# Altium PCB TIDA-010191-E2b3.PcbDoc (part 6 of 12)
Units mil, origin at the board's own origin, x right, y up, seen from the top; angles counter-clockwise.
Board outline 9842.52 x 9842.4 mil, 6 copper layers (Layer 1 - Top Layer, Layer 2 - GND Layer, Layer 3 - Signal, Layer 4 - Signal, Layer 5 - GND, Bottom Layer), stack 59.9 mil thick; 1178 components, 642 nets, 3329 pads, 2967 vias.
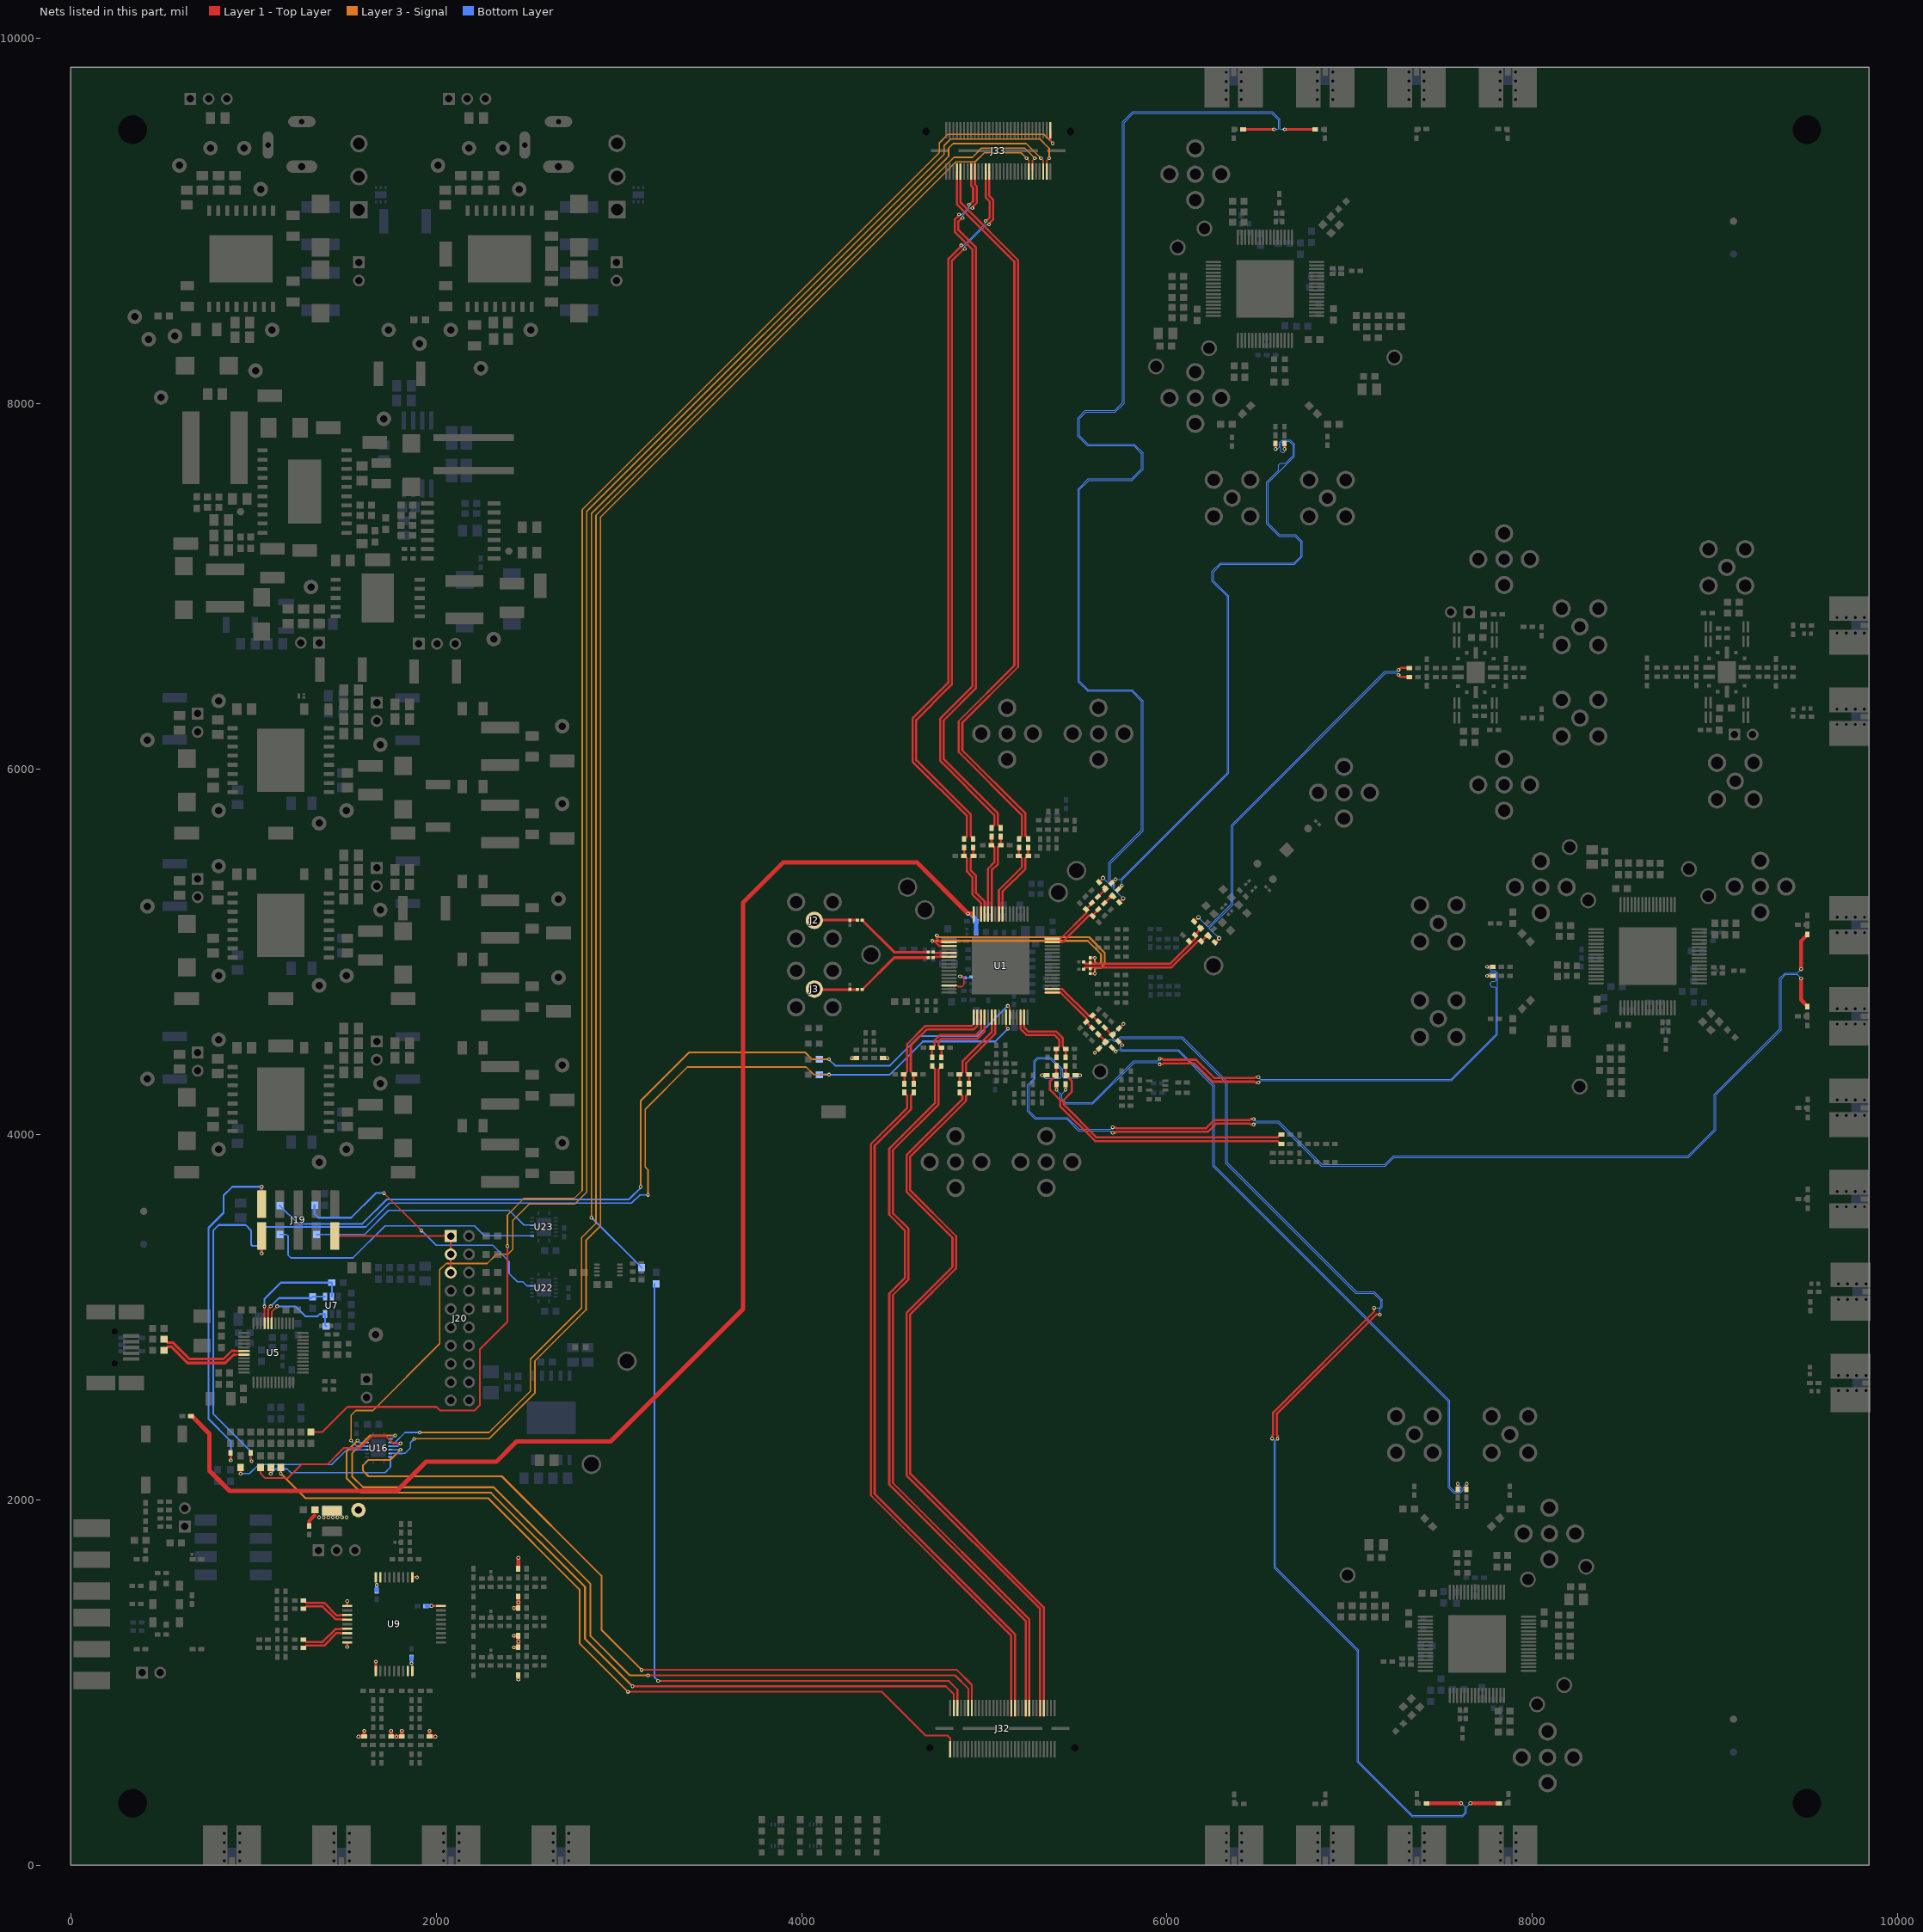
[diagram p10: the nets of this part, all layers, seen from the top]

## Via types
v1: diameter 20, hole 10, Layer 1 - Top Layer to Bottom Layer, tented both sides, 2595 vias
v2: diameter 19.68, hole 7.87, Layer 1 - Top Layer to Bottom Layer, 308 vias
v3: diameter 19.68, hole 7.87, Layer 1 - Top Layer to Bottom Layer, tented both sides, 25 vias
v4: diameter 20, hole 10, Layer 1 - Top Layer to Bottom Layer, 21 vias
v5: diameter 41, hole 25, Layer 1 - Top Layer to Bottom Layer, 10 vias
v6: diameter 24, hole 12, Layer 1 - Top Layer to Bottom Layer, tented both sides, 4 vias
v7: diameter 24, hole 8, Layer 1 - Top Layer to Bottom Layer, tented both sides, 1 vias
v8: diameter 24/24/24/24/24/24 (per signal layer), hole 8, Layer 1 - Top Layer to Bottom Layer, tented both sides, 1 vias
v9: diameter 30, hole 12, Layer 1 - Top Layer to Bottom Layer, tented both sides, 1 vias
v10: diameter 20/20/20/20/20/20 (per signal layer), hole 10, Layer 1 - Top Layer to Bottom Layer, tented both sides, 1 vias

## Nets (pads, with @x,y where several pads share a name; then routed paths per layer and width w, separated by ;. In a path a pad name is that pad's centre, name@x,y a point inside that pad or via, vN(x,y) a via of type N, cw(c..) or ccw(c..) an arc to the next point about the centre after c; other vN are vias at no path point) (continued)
C_VCC: C93.1 C94.1 C95.1 C96.1 C97.1 L17.2 R175.2 R395.2 R396.2 R428.2 R429.2 R438.2 R439.2 R448.2 R449.2 R458.2 R459.2 R468.2 R469.2 TP8.1 U9.1 U9.9 U9.10 U9.17 U9.18 U9.27 U9.28 U9.35 U9.36 | length 923.2
  Layer 1 - Top Layer w12: v1(1513.58,1195) U9.9@1513.58,1220.48 ; U9.1@1513.58,1420.48 v1(1513.58,1445.96) ; U9.10@1670.08,1063.98 v1(1670.08,1115.56) ; U9.28@1870.08,1576.98 v1(1895.56,1576.98) ; v1(1975,1420.48) U9.27@2026.58,1420.48
  Layer 1 - Top Layer w20: R175.2@1305,1858.62 1305,1885 1335,1915 ; v1(1575.09,705) R396.2@1606.38,705 v1(1606.38,736.28) ; v1(1753.62,736.28) R395.2@1753.62,705 v1(1783,705) R429.2@1812.38,705 v1(1812.38,736.28) ; v1(1964.62,736.28) R428.2@1964.62,705 v1(1995.91,705) ; v1(2425,1193.62) R469.2@2450,1193.62 v1(2450,1225) R459.2@2450,1256.38 v1(2425,1256.38) ; v1(2425,1408.62) R458.2@2450,1408.62 v1(2450,1440) R449.2@2450,1471.38 ; v1(2450,1016.38) R468.2@2450,1041.38 ; R448.2@2450,1623.62 v1(2450,1683.54) ; v1(4275.38,4418.76) R438.2@4300.38,4418.76 ; R439.2@4444.62,4418.76 v1(4469.62,4418.76)
  Bottom Layer w20: C95.1@1675,1503.62 v1(1675,1535) ; v1(1865.15,1105.96) C97.1@1865.15,1137.34 ; C96.1@1945,1420 1945.48,1420.48 v1(1975,1420.48)
  other v1: 1360,1905 1385,1905 1410,1905 1435,1905 1460,1905 1485,1905 1510,1905
CDCLVP_CLK1_N: R220.2 U9.7 | length 275
  Layer 1 - Top Layer w12: R220.2@1273.62,1190.96 1277.56,1190.96 1290.06,1203.46 1386.78,1203.46 1456.3,1272.98 1476.98,1272.98 1479.48,1270.48 U9.7@1513.58,1270.48
CDCLVP_CLK1_P: R180.2 U9.6 | length 275
  Layer 1 - Top Layer w12: R180.2@1273.62,1235.96 1277.56,1235.96 1290.06,1223.46 1378.5,1223.46 1448.02,1292.98 1477.02,1292.98 1479.52,1295.48 U9.6@1513.58,1295.48
CDCM7005-SP_VCXO_IN_N: R36.2 U9.4 | length 275
  Layer 1 - Top Layer w12: R36.2@1273.62,1405 1277.56,1405 1290.06,1417.5 1378.5,1417.5 1448.02,1347.98 1477.02,1347.98 1479.52,1345.48 U9.4@1513.58,1345.48
CDCM7005-SP_VCXO_IN_P: R38.2 U9.3 | length 275
  Layer 1 - Top Layer w12: R38.2@1273.62,1450 1277.56,1450 1290.06,1437.5 1386.78,1437.5 1456.3,1367.98 1476.98,1367.98 1479.48,1370.48 U9.3@1513.58,1370.48
CLKIN0_N: C37.2 U1.38 | length 81.2
  Layer 1 - Top Layer w12: C37.2@4719.88,4969.09 4722.15,4971.36 4725.36,4971.36 4728.09,4974.09 U1.38@4799.04,4974.09
CLKIN0_P: C36.2 U1.37 | length 89.5
  Layer 1 - Top Layer w12: C36.2@4719.88,4999.09 4722.15,4996.83 4725.17,4996.83 4727.9,4994.09 U1.37@4807.32,4994.09
CLKin1_N: R556.2 U1.35 | length 1191
  Layer 1 - Top Layer w12: v1@4715,5060 4726.72,5060 4753.45,5033.27 U1.35@4807.52,5033.27 ; R556.2@5580,4967.99 v1@5604.9,4967.99
  Layer 3 - Signal w10.5: v1(4715.42,5060.42) 5566.2,5060.42 5639.41,4987.21 5639.41,4943.28 5631.12,4935 5616,4935 5605.17,4945.83 v1(5605.17,4967.99)
CLKIN1_P: R555.2 U1.34 | length 1260.7
  Layer 1 - Top Layer w12: v1@4740,5090 4740,5075 4762,5053 U1.34@4844,5053 ; R555.2@5580,4882.01 v1@5604.9,4882.01
  Layer 3 - Signal w10.5: v1(4740.42,5089.66) 4749.02,5081.06 5573.83,5081.06 5659.41,4995.48 5659.41,4935 5639.41,4915 5616,4915 5605.17,4904.17 v1(5605.17,4882.01)
CLKin1c_N: C39.2 C40.2 C80.2 R145.2 R554.1 R556.1 | length 740.5
  Layer 1 - Top Layer w12: R554.1@5542.99,4945 5553.15,4934.84 6016.56,4934.84 6155,5073.28 6155,5094.96 C39.2@6187.04,5127
CLKin1c_P: C38.2 C79.2 R145.1 R553.1 R555.1 | length 755.2
  Layer 1 - Top Layer w12: R553.1@5542.99,4905 5553.15,4915.16 6024.71,4915.16 R145.1@6168.92,5059.36 ; R145.1@6170,5060 6190.04,5060 C38.2@6222.04,5092
CLKin1d_N: C80.1 R131.2 | length 2048.6
  Layer 1 - Top Layer w4.25: v6@6171.21,5189.62 v6(6171.89,5189.62)
  Layer 1 - Top Layer w12: C80.1@6148.3,5166.7 v6@6171.21,5189.62 ; v1(7267,6543.5) 7278.5,6555 R131.2@7326.38,6555
  Bottom Layer w4.25: v6(6171.89,5189.62) 6223.37,5138.14 6226.89,5138.14 6351.75,5263 6351.75,5694.62 7192.38,6535.25 7256.87,6535.25 7265.12,6543.5 v1(7267,6543.5)
CLKin1d_P: C79.1 R121.2 | length 2044
  Layer 1 - Top Layer w12: C79.1@6261.7,5053.3 v6@6284.4,5075.99 ; v1(7267,6516.5) 7278.5,6505 R121.2@7326.38,6505
  Bottom Layer w4.25: v6(6285.23,5075.08) 6232.83,5127.48 6232.83,5131 6361,5259.17 6361,5690.79 7196.21,6526 7257.5,6526 v1(7267,6516.5) v1@7265.62,6516.5
CLKIN_SEL0: R78.1 R296.2 U1.58 | length 5018.6
  Layer 1 - Top Layer w8: U1.58@5119.53,4642.52 5119.53,4590.47 5129,4581 v1(5129,4580)
  Layer 3 - Signal w8: v1(3160,3670.59) 3160,3807.25 3144,3823.25 3144,4139 3375,4370 4025,4370 4066.54,4328.46 v1(4150,4328.46)
  Bottom Layer w8: R296.2@1045,3454.06 1045,3485 1055,3495 1615,3495 1745,3625 3070,3625 3115.59,3670.59 v1(3160,3670.59)
  Bottom Layer w10: v1(4150,4328.46) 4482.84,4328.46 4664.38,4510 5060,4510 5129,4579 v1(5129,4580)
  Bottom Layer w10.5: R78.1@4098.39,4328.46 v1(4150,4328.46)
CLKIN_SEL1: R77.1 R307.1 U1.59 | length 4983
  Layer 1 - Top Layer w8: v1(5128.74,4705.04) 5139.21,4694.57 U1.59@5139.21,4642.52
  Layer 3 - Signal w10: v1(3120,3715) 3120,4185 3385,4450 4020,4450 4058,4412 v1(4150,4412)
  Bottom Layer w10: R307.1@1145,3611.56 1245,3511.56 1596.56,3511.56 1730,3645 3055,3645 3125,3715 v1(3120,3715) ; v1(4150,4412) 4184,4378 4484,4378 4646,4540 4963.7,4540 v1(5128.74,4705.04)
  Bottom Layer w10.5: R77.1@4098.39,4412 v1(4150,4412)
CLKINN0: J3.1 R100.1 R101.1 | length 237.1
  Layer 1 - Top Layer w15: J3.1@4073.26,4793.74 R101.1@4305.75,4793.74
  Layer 1 - Top Layer w24: J3.1@4070,4797 J3.1@4073.26,4793.74
CLKINN1: C37.1 R101.2 | length 430.9
  Layer 1 - Top Layer w15: R101.2@4331.73,4793.74 4507.09,4969.09 C37.1@4690,4969.09
CLKINP0: J2.1 R98.1 R99.2 | length 232.5
  Layer 1 - Top Layer w15: J2.1@4073.26,5174.45 R98.1@4305.75,5174.45
CLKINP1: C36.1 R98.2 | length 430.9
  Layer 1 - Top Layer w15: R98.2@4331.73,5174.45 4507.09,4999.09 C36.1@4690,4999.09
CPOUT1: C17.1 C186.2 R33.2 U1.32 | length 7542.1
  Layer 1 - Top Layer w24: R33.2@658.62,2460 662.56,2460 760,2362.56 760,2160 870,2050 1785,2050 1945,2210 2330,2210 2440,2320 2955,2320 3680,3045 3680,5270 3900,5490 4631.65,5490 v1@4911.21,5210.44 ; v1(4911.41,5209.62) 4936.27,5209.62
  Bottom Layer w24: v1@4912.64,5209.82 4924.48,5209.82 4949.57,5184.73 4949.57,5168.76 4949.76,5168.58 C17.1@4953.32,5168.58 4954.62,5168.58 4954.81,5168.39 4954.81,5105.19 C186.2@4955,5105
CPOUT2: C7.1 C8.2 U1.46 | length 218.5
  Layer 1 - Top Layer w8: U1.46@4807.52,4816.73 4808.25,4816 4853.57,4816 4859.85,4809.72 4877.83,4809.72 4887.73,4819.62 4887.73,4860.82 4882.19,4866.36 v1(4866.97,4866.36)
  Bottom Layer w8: v1@4866.8,4865.99 4870.58,4865.99 4878.32,4858.26 C8.2@4894.36,4858.26 4905.63,4858.26 4906.03,4858.65 4922.74,4858.65 C7.1@4927.01,4862.92 ; v1@4867.31,4867.83 v1@4867.97,4867.16 ; C8.2@4894.61,4854.65 C8.2@4894.61,4855.44
D_N: R149.2 U5.6 | length 501.1
  Layer 1 - Top Layer w11: 898,2817 899.57,2815.43 U5.6@948.58,2815.43
  Layer 1 - Top Layer w15: R149.2@511.5,2880 512.48,2880 531.48,2861 561,2861 650,2772 837,2772 882,2817 898,2817
D_P: R150.2 U5.7 | length 500.5
  Layer 1 - Top Layer w11: 898,2795.75 U5.7@948.58,2795.75
  Layer 1 - Top Layer w15: R150.2@511.5,2820 512.48,2820 531.48,2839 551.89,2839 640.89,2750 846.11,2750 891.11,2795 898,2795
DCLKout0*_N: R71.1 R242.2 | length 3530.1
  Layer 1 - Top Layer w12: R71.1@5733.7,4511.3 v1(5754.5,4490.5) ; R242.2@7590.47,2057.68 v1(7590.47,2088.59)
  Bottom Layer w4.25: v1(5754.5,4490.5) 5744,4480 5744,4473.02 5751.02,4466 6063.04,4466 6260,4269.04 6260,3831.02 7548.5,2542.52 7548.5,2071.5 7571.5,2048.5 7603.5,2048.5 7611.03,2056.03 7611.03,2068.04 v1(7590.47,2088.59)
DCLKout0*_P: R68.1 R238.2 | length 3551.8
  Layer 1 - Top Layer w12: R68.1@5698.7,4476.3 v1(5719.5,4455.5) ; R238.2@7639.97,2057.68 v1(7639.97,2088.59)
  Bottom Layer w4.25: v1(5719.5,4455.5) 5730,4466 5739,4466 5747.5,4457.5 6059.52,4457.5 6251.5,4265.52 6251.5,3827.5 7540,2539 7540,2067.98 7567.98,2040 7607.02,2040 7619.42,2052.4 7619.42,2068.04 v1(7639.97,2088.59)
DCLKOUT0+: C5.1 R32.2 U1.1 | length 340.7
  Layer 1 - Top Layer w12: U1.1@5336,4777.31 5417.68,4777.31 5557.5,4637.5 5559.49,4635.51 R32.2@5559.49,4619.49 ; R32.2@5558.3,4616.7 C5.1@5588.3,4586.7
DCLKOUT0-: C6.1 R31.2 U1.2 | length 357.6
  Layer 1 - Top Layer w12: U1.2@5336,4797.05 5426.24,4797.05 5571.64,4651.64 5572.77,4650.51 R31.2@5590.51,4650.51 ; R31.2@5591.9,4651.11 C6.1@5621.9,4621.11
DCLKout0_LMK_N: R69.1 R236.2 | length 6403.9
  Layer 1 - Top Layer w10: R69.1@5737.61,4582.2 v1@5761.58,4606.18
  Layer 1 - Top Layer w12: v1(6605.5,2336.21) 6605.5,2351.21 6600.5,2356.21 6600.5,2470.5 7145,3015 v1(7165,3015)
  Layer 1 - Top Layer w22: R236.2@7420.81,340 v1(7610,340)
  Bottom Layer w4.25: v1@5761,4607 5761,4605.87 5706.01,4550.89 5706.01,4526.01 5713.52,4518.5 5729.06,4518.5 5745.56,4535 6083.3,4535 6330,4288.3 6330,3846 7036,3140 7134,3140 7178.5,3095.5 7178.5,3056.48 7165,3042.98 v1(7165,3015) ; 6595,2325.21 6595,1631.66 7049.35,1177.31 7049.35,569.33 7343.68,275 7614.77,275 7631.09,291.32 7631.09,318.91 v1(7610,340) ; 6595,2325.71 v1(6605.5,2336.21)
  other v1: 5761.33,4606.21
DCLKout0_LMK_P: R26.1 R234.2 | length 6423.2
  Layer 1 - Top Layer w10: v1@5605.15,4447.76 R26.1@5629.12,4471.74
  Layer 1 - Top Layer w12: v1(6575.5,2336.21) 6575.5,2351.21 6580.5,2356.21 6580.5,2478.78 7133.36,3031.64 v1(7133.36,3051.64)
  Layer 1 - Top Layer w22: v1(7660.61,340) R234.2@7816.56,340
  Bottom Layer w4.25: v1@5604,4450 5674,4520 5700,4520 5710,4510 5732.59,4510 5749.08,4526.5 6079.78,4526.5 6321.5,4284.78 6321.5,3842.48 7032.48,3131.5 7130.48,3131.5 7170,3091.98 7170,3060 7161.64,3051.64 v1(7133.36,3051.64) ; v1(6575.5,2336.21) 6586.5,2325.21 6586.5,1628.14 7040.85,1173.79 7040.85,565.81 7045.83,560.83 7340.16,266.5 7618.29,266.5 7639.59,287.8 7639.59,318.91 ; 7639.59,318.98 v1(7660.61,340)
  other v1: 5604.9,4447.7
DCLKOUT0_N: C6.2 R69.2 R71.2 | length 63.1
  Layer 1 - Top Layer w12: C6.2@5658.7,4586.3 5700.2,4544.8 R71.2@5700.3,4544.7 R71.2@5703.3,4541.7
DCLKOUT0_P: C5.2 R26.2 R68.2 | length 62.4
  Layer 1 - Top Layer w12: C5.2@5623.7,4550.3 R68.2@5667.8,4506.2
DCLKout2*_N: R81.1 R350.2 | length 3543.2
  Layer 1 - Top Layer w12: R81.1@5696.7,5376.7 v1(5717.5,5397.5) ; v1(6643.38,7752.91) R350.2@6643.38,7783.82
  Bottom Layer w4.25: v1(5717.5,5397.5) 5746.48,5397.5 6330,5981.02 6330,6944.98 6247.3,7027.68 6247.3,7031.2 6247.3,7084.32 6292.98,7130 6695,7130 6732.5,7167.5 6732.5,7242.5 6700,7275 6612.98,7275 6545,7342.98 6545,7572.02 6610,7637.02 6610,7665 6620,7675 6647.98,7675 6690,7717.02 6690,7775 6670,7795 6634.02,7795 6622.93,7783.91 6622.93,7742.07 6630,7735 6640,7735 6645,7740 v1@6645,7750
DCLKout2*_P: R75.1 R325.2 | length 3527.9
  Layer 1 - Top Layer w12: R75.1@5731.7,5341.7 v1(5752.5,5362.5) ; v1(6593.88,7752.91) R325.2@6593.88,7783.82
  Bottom Layer w4.25: v1(5752.5,5362.5) 5752.5,5391.5 6338.5,5977.5 6338.5,6948.5 6255.8,7031.2 6255.8,7080.8 6296.5,7121.5 6686.5,7121.5 ; v1(6593.88,7752.91) 6602.91,7752.91 6614.43,7764.43 6614.43,7787.43 6630.5,7803.5 6673.52,7803.5 6698.5,7778.52 6698.5,7713.5 6553.5,7568.5 6553.5,7346.5 6616.5,7283.5 6703.52,7283.5 6741,7246.02 6741,7176 ; 6686.5,7121.5 6698.52,7121.5 6741,7163.98 6741,7176
DCLKOUT2+: C15.1 R48.2 U1.15 | length 366.6
  Layer 1 - Top Layer w12: U1.15@5336,5052.95 5426.24,5052.95 5571.64,5198.36 5572.77,5199.49 5590.51,5199.49 R48.2@5593.3,5196.7 ; R48.2@5591.9,5198.89 5621.9,5228.89 C15.1@5626.9,5228.89
DCLKOUT2-: C16.1 R47.2 U1.16 | length 349.6
  Layer 1 - Top Layer w12: U1.16@5336,5072.68 5417.68,5072.68 5557.5,5212.5 5559.49,5214.49 5559.49,5230.51 R47.2@5556.7,5233.3 ; R47.2@5558.3,5233.3 5588.3,5263.3 C16.1@5588.3,5268.3
DCLKout2_LMK_N: R76.1 R275.2 | length 6574.3
  Layer 1 - Top Layer w10: R76.1@5627.89,5382.89 v6@5649.6,5404.6
  Layer 1 - Top Layer w15: v1(6644.36,9502.98) R275.2@6811.25,9502.98
  Bottom Layer w4.25: 5628,7590 5568.98,7590 5513.5,7534.52 5513.5,6478.5 5565,6427 5805,6427 5860.5,6371.5 5860.5,5667.52 5681.5,5488.52 5681.5,5388.89 5706.18,5364.21 5706.18,5360.69 5701.69,5356.2 5698.17,5356.2 v6@5653.38,5400.99 ; 5628,7590 5805.96,7590 5860,7644.04 5860,7727.91 5816.91,7771 5564.42,7771 5512,7823.42 5512,7923.19 5552.8,7963.99 5713.99,7963.99 5756.5,8006.5 5756.5,9543.42 5813.08,9600 6576.53,9600 6619.08,9557.45 6619.08,9505.47 6621.57,9502.98 v1(6644.36,9502.98)
  other v6: 5649.6,5404.77
DCLKout2_LMK_P: R74.1 R248.2 | length 6566.6
  Layer 1 - Top Layer w10: R74.1@5738.41,5271.41 v6@5760.12,5293.12
  Layer 1 - Top Layer w15: R248.2@6417.08,9502.98 v1(6585.3,9502.98)
  Bottom Layer w4.25: v6(5760.12,5293.29) 5707.22,5346.19 5707.22,5349.71 5714.68,5357.17 5714.68,5367.73 5690,5392.41 5690,5485 5869,5664 5869,6375.02 5808.52,6435.5 5568.52,6435.5 5522,6482.02 5522,7531 5572.5,7581.5 5809.48,7581.5 5858,7630.02 5868.5,7640.52 5868.5,7731.43 5820.43,7779.5 5567.94,7779.5 5520.5,7826.94 5520.5,7919.67 5556.32,7955.49 5717.51,7955.49 5765,8002.98 5765,9539.9 5816.6,9591.5 6573.01,9591.5 6610.58,9553.93 6610.58,9505.47 6608.09,9502.98 v1(6585.3,9502.98)
DCLKOUT2_N: C16.2 R76.2 R81.2 | length 58.8
  Layer 1 - Top Layer w12: C16.2@5621.7,5301.7 R81.2@5663.3,5343.3
DCLKOUT2_P: C15.2 R74.2 R75.2 | length 58.8
  Layer 1 - Top Layer w12: C15.2@5656.7,5266.7 R75.2@5698.3,5308.3
DCLKout12*_N: R132.1 R301.2 | length 3191.1
  Layer 1 - Top Layer w12: v1(5445,4245) R132.1@5445,4276.38 ; v1(5960,4415) 5975,4415 5980,4410 6158.28,4410 6258.28,4310 6480,4310 6485,4315 v1(6500,4315) ; v1(7751.71,4868.8) R301.2@7782.62,4868.8
  Bottom Layer w4.25: v1(5445,4245) 5424,4224 5424,4198.02 5445.33,4176.69 5591.69,4176.69 5818.52,4403.52 5948.52,4403.52 v1(5960,4415) ; v1(6500,4315) 6511,4304 7554,4304 7801,4551 7801,4802.1 7794.5,4808.6 7776.4,4808.6 7770,4815 7770,4830 7778.6,4838.6 7794.5,4838.6 7801,4845.1 7801,4880 7791.75,4889.25 7772.16,4889.25 v1(7751.71,4868.8)
DCLKout12*_P: R127.1 R295.2 | length 3186.8
  Layer 1 - Top Layer w12: v1(5395,4245) R127.1@5395,4276.38 ; v1(5960,4385) 5975,4385 5980,4390 6150,4390 6250,4290 6480,4290 6485,4285 v1(6500,4285) ; v1(7751.71,4918.3) R295.2@7782.62,4918.3
  Bottom Layer w4.25: v1(5395,4245) 5415.5,4224.5 5415.5,4194.5 5441.81,4168.19 5595.21,4168.19 5822.04,4395.02 5949.98,4395.02 v1(5960,4385) ; v1(6500,4285) 6510.5,4295.5 7557.52,4295.5 7809.5,4547.48 7809.5,4883.52 7795.27,4897.75 7772.26,4897.75 v1(7751.71,4918.3)
DCLKout12_LMK_N: R130.1 R229.2 | length 5949.5
  Layer 1 - Top Layer w12: v1(5702.4,4010.03) 5717.4,4010.03 5722.4,4015.03 5761.11,4015.03 ; 5761.33,4015 6222.78,4015 6268.28,4060.5 6454,4060.5 6459,4055.5 v1(6474,4055.5)
  Layer 1 - Top Layer w20: R130.1@5498.62,4325 v1(5523.62,4325) ; v1(9470.1,4855) 9470.1,4738.17 9503.38,4704.9 R229.2@9503.38,4701
  Bottom Layer w4.25: v1(5523.62,4325) 5508.82,4310.19 5433.7,4310.19 5428.89,4315 5428.89,4358.13 5363.52,4423.5 5291.48,4423.5 5271.5,4403.52 5271.5,4308.52 5236.5,4273.52 5236.5,4126.48 5277.07,4085.91 5450.02,4085.91 5514.39,4021.53 5690.9,4021.53 v1(5702.4,4010.03) ; v1(6474,4055.5) 6485,4066.5 6546.53,4066.5 6606.5,4066.5 6845.02,3827.98 7194.81,3827.98 7241.83,3875 8854.35,3875 9003.72,4024.37 9003.72,4217.17 9360.81,4574.26 9360.81,4851.43 9385.87,4876.5 9448.5,4876.5 v1@9470.05,4854.95
DCLKout12_LMK_P: R126.1 R223.2 | length 5949.3
  Layer 1 - Top Layer w12: v1(5702.4,4040.03) 5717.4,4040.03 5722.4,4035.03 5761.11,4035.03 ; 5761.33,4035 6214.5,4035 6260,4080.5 6454,4080.5 6459,4085.5 v1(6474,4085.5)
  Layer 1 - Top Layer w20: v1(5316.38,4325) R126.1@5341.38,4325 ; v1@9470,4910.93 9470,5059.6 9503.27,5092.87 R223.2@9503.27,5096.76
  Bottom Layer w4.25: v1(5316.38,4325) 5333.7,4307.67 5412.98,4307.67 5420.39,4315.09 5420.39,4354.61 5360,4415 5295,4415 5280,4400 5280,4305 5245,4270 5245,4130 5280.59,4094.41 5453.54,4094.41 5517.91,4030.03 5692.4,4030.03 v1(5702.4,4040.03) ; v1(6474,4085.5) 6484.5,4075 6543.01,4075 6610.02,4075 6848.54,3836.48 7191.29,3836.48 7238.31,3883.5 8850.83,3883.5 8995.22,4027.89 8995.22,4220.69 9352.31,4577.78 9352.31,4854.95 9382.35,4885 9449.07,4885 v1(9470,4905.93)
DCLKOUT12_N: C4.2 R130.2 R132.2 R391.1 | length 1528.8
  Layer 1 - Top Layer w12: C4.2@5445,4376.38 R132.2@5445,4323.62 5445,4319.68 5450.81,4313.87 5458.54,4313.87 5480,4292.41 5480,4235 5435,4190 5435,4165 5615,3985 6437.58,3985 ; 6430,3985 6437.58,3985 ; R391.1@6626.38,4000 6619.45,4000 6604.45,3985 6437.58,3985
DCLKOUT12_P: C3.2 R126.2 R127.2 R393.1 | length 1556.2
  Layer 1 - Top Layer w12: C3.2@5395,4376.38 R127.2@5395,4323.62 5391.08,4323.62 5360,4292.54 5360,4245 5415,4190 5415,4156.72 5606.72,3965 6604.45,3965 6619.45,3950 R393.1@6626.38,3950
DCLKout12a_N: C4.1 R21.2 U1.63 | length 442.4
  Layer 1 - Top Layer w12: U1.63@5217.95,4679 U1.63@5217.95,4642.52 5217.95,4587.05 5240.27,4564.73 5393.17,4564.73 5429.73,4528.17 5429.73,4482.71 5436.63,4475.81 5442.44,4470 R21.2@5446.38,4470 5446.38,4425 C4.1@5445,4423.62
DCLKout12a_P: C3.1 R22.2 U1.62 | length 442.3
  Layer 1 - Top Layer w12: U1.62@5198.22,4679 5198.22,4578.87 5232.09,4545 5385,4545 5410,4520 5410,4482.44 5403.37,4475.81 5397.56,4470 R22.2@5393.62,4470 5393.62,4425 C3.1@5395,4423.62
E_SCL: J19.9 R172.2 R211.1 | length 1945.6
  Layer 1 - Top Layer w10: R172.2@875,2258.38 875.7,2257.67 875.7,2217.84 v1(876.41,2217.13)
  Layer 1 - Top Layer w13.5: J19.9@1045,3620.06 v1(1045,3715)
  Bottom Layer w10: v1(876.41,2217.13) 876.41,2321.74 755,2443.15 755,3490 837,3572 837,3667 885,3715 v1(1045,3715) ; R211.1@1040.86,3669.91 R211.1@1045,3674.06
  Bottom Layer w13.5: R211.1@1045,3674.06 v1(1045,3715)
E_SDA: J19.10 R173.2 R296.1 | length 1908.5
  Layer 1 - Top Layer w10: R173.2@986,2258.38 986,2216.55 v1@989.31,2213.24 ; v1(990.09,2211.68) v1@992.43,2211.68
  Layer 1 - Top Layer w13.5: v1(1045,3350.12) J19.10@1045,3445.06
  Bottom Layer w10: v1(990.09,2211.68) 992.8,2211.68 986,2218.48 986,2265.87 907,2344.87 907,2345 780,2472 780,3475 810,3505 957.5,3505 987.5,3475 987.5,3398.29 994.72,3391.06 R296.1@1045,3391.06
  Bottom Layer w13.5: v1(1045,3350.12) R296.1@1045,3391.06
EECLK: R162.1 U5.44 U7.4 | length 418.5
  Layer 1 - Top Layer w10: U5.44@1080.47,2967.01 1080.47,3045.47 v1(1095,3060)
  Bottom Layer w10: v1(1095,3060) 1140,3105 1317.91,3105 R162.1@1325,3112.09 1325.75,3112.83 U7.4@1392.6,3112.83
EECS: R161.1 U5.45 U7.5 | length 616.2
  Layer 1 - Top Layer w10: U5.45@1060.79,2967.01 v1(1060.79,3060)
  Bottom Layer w10: v1(1060.79,3060) 1060.79,3100.79 1150,3190 R161.1@1428.5,3190 1430,3188.5 U7.5@1430,3112.83
EEDATA: R163.1 U5.43 U7.3 | length 466.5
  Layer 1 - Top Layer w10: U5.43@1100.16,2967.01 1100.16,3030.16 v1(1130,3060)
  Bottom Layer w10: v1(1130,3060) 1230,3060 1285,3005 1350,3005 1363.35,3018.35 U7.3@1392.6,3018.35 1392.6,2956.5 R163.1@1398.5,2950.59
ELMK_CS: J19.2 J20.1 J20.3 J20.5 | length 835.4
  Layer 1 - Top Layer w10: J19.2@1445,3446.06 1446.06,3445 J20.1@2080,3445 J20.3@2080,3345 J20.5@2080,3245
ELMK_SCK: R302.1 U23.2 | length 1589.9
  Bottom Layer w8: R302.1@1145,3454.06 1180.94,3454.06 1190,3445 1190,3340 1205,3325 1545,3325 1720,3500 2210,3500 2264.21,3445.79 U23.2@2525.04,3445.79
ELMK_SDIO: R303.1 U23.5 | length 1267.5
  Bottom Layer w8: R303.1@1345,3454.06 1609.06,3454.06 1740,3585 2400,3585 2480.16,3504.84 U23.5@2525.04,3504.84
ELMK_SDO: R305.1 U22.5 | length 1551.1
  Layer 1 - Top Layer w8: v1(1715,3680) v1(1920,3475)
  Bottom Layer w8: v1(1920,3475) 2000,3395 2310,3395 2400,3305 2400,3240 2445,3195 2475,3195 2497.6,3172.4 U22.5@2525.04,3172.4
  Bottom Layer w10: R305.1@1335,3613.5 1335,3565 1355,3545 1535,3545 1670,3680 v1(1715,3680)
F_CORECLK1+: R18.2 R182.1 U1.51 | length 484.7
  Layer 1 - Top Layer w12: R182.1@4715,4423.62 4713.62,4425 R18.2@4713.62,4475 4717.56,4475 4729.27,4486.71 4729.27,4517.27 4756.73,4544.73 4953.73,4544.73 4981.69,4572.69 U1.51@4981.69,4679
F_CORECLK1-: R17.2 R70.1 U1.52 | length 485.4
  Layer 1 - Top Layer w12: R70.1@4765,4423.62 4766.38,4425 R17.2@4766.38,4475 4762.44,4475 4749,4488.44 4749,4509.09 4764.91,4525 4961.91,4525 5001.42,4564.51 U1.52@5001.42,4679
F_CORECLK1_N: J32.15 R70.2 | length 4046.9
  Layer 1 - Top Layer w12: R70.2@4765,4376.38 4765,4372.44 4750,4357.44 4750,4165 4500,3915 4500,3570 4585,3485 4585,3206.72 4500,3121.72 4500,2093.28 5246.92,1346.36 J32.15@5246.92,819
F_CORECLK1_P: J32.17 R182.2 | length 4046.9
  Layer 1 - Top Layer w12: R182.2@4715,4376.38 4715,4372.44 4730,4357.44 4730,4173.28 4480,3923.28 4480,3561.72 4565,3476.72 4565,3215 4480,3130 4480,2085 5226.92,1338.08 J32.17@5226.92,819
F_CORECLK2+: R67.2 R184.1 U1.27 | length 481.4
  Layer 1 - Top Layer w12: U1.27@5040.83,5171 5040.83,5447.55 5075,5481.72 5075,5572.56 5088.82,5586.38 5090,5586.38 R184.1@5090,5631.38
F_CORECLK2-: R66.2 R183.1 U1.28 | length 480.8
  Layer 1 - Top Layer w12: U1.28@5021.1,5171 5021.1,5456.1 5055,5490 5055,5572 ; R183.1@5040,5631.38 5040,5586.38 5041.18,5586.38 5055,5572.56
F_CORECLK2_N: J33.15 R183.2 | length 3938.6
  Layer 1 - Top Layer w12: v1(4861.91,9037.09) 4861.91,9034.93 4857.91,9030.93 4857.91,9028.14 4838,9008.23 4838,8943.24 4935,8846.24 4935,6453.28 4758,6276.28 4758,6047 5055,5750 5055,5695.4 5047.97,5688.37 5045.81,5688.37 5040,5682.56 R183.2@5040,5678.62 ; v1(4915.91,9091.09) 4918.07,9091.09 4922.07,9095.09 4924.86,9095.09 4938.91,9109.14 4938.91,9183.46 4928.66,9193.71 4928.66,9272.88 J33.15@4928.82,9272.88 ; J33.15@4928.82,9316 J33.15@4928.82,9272.88 ; J33.15@4929.11,9272.88 J33.15@4928.98,9272.88 J33.15@4928.82,9272.88
  Bottom Layer w3.75: v1(4861.91,9037.09) 4875.34,9037.09 4892.8,9054.55 4915.91,9077.66 v1(4915.91,9091.09)
F_CORECLK2_P: J33.17 R184.2 | length 3938.6
  Layer 1 - Top Layer w12: v1(4881,9018) 4878.84,9018 4874.84,9014 4872.05,9014 4858,8999.95 4858,8951.52 4955,8854.52 4955,6445 4778,6268 4778,6055.28 5075,5758.28 5075,5695.4 5082.03,5688.37 5084.19,5688.37 5090,5682.56 R184.2@5090,5678.62 ; v1(4935,9072) 4935,9074.16 4939,9078.16 4939,9080.95 4958.91,9100.86 4958.91,9191.75 4948.66,9201.99 J33.17@4948.66,9272.88 J33.17@4948.82,9272.88 ; J33.17@4948.82,9316 J33.17@4948.82,9272.88 ; J33.17@4949.11,9272.88 J33.17@4948.82,9272.88
  Bottom Layer w3.75: v1(4881,9018) 4881,9031.43 4900.8,9051.23 4921.57,9072 v1(4935,9072)
F_LMK_CSB: R187.2 U16.7 | length 776.2
  Layer 1 - Top Layer w10: v1(1095,2144.41) R187.2@1095,2178.5
  Bottom Layer w8: v1(1095,2144.41) 1120.59,2170 1185.07,2170 1205.07,2150 1720,2150 1749.96,2179.96 U16.7@1749.96,2235.79
F_LMK_LMX_CLK: R185.2 U16.12 | length 778.3
  Layer 1 - Top Layer w10: v1(930,2144.41) R185.2@930,2178.5
  Bottom Layer w8: v1(930,2144.41) 930.59,2145 980,2145 1030,2195 1429.68,2195 1509.84,2275.16 U16.12@1620.04,2275.16
F_LMK_LMX_DATA: R186.2 U16.4 | length 982.4
  Layer 1 - Top Layer w10: R186.2@1040,2178.5 1040,2144.41 1064.41,2120 1187.99,2120 1262.99,2195 1405,2195 1495,2285 1585,2285 1650,2350 1725,2350 1765,2310 v1(1805,2310)
  Bottom Layer w8: U16.4@1749.96,2294.84 1789.84,2294.84 v1(1805,2310)
F_LMX1_SDO: J32.55 R189.1 | length 3939.6
  Layer 1 - Top Layer w10: v1(3215,1010) 4805,1010 4853.06,961.94 J32.55@4853.06,862.12
  Bottom Layer w10: R189.1@3195,3183.5 3195,1030 v1(3215,1010)
F_LMX2_SDO: J33.55 R225.1 | length 7679
  Layer 1 - Top Layer w8: v1(5310.04,9345) 5322.68,9332.36 J33.55@5322.68,9272.88
  Layer 3 - Signal w8: v1(2850,3545) 2850,7400.71 4781.71,9332.41 4805,9355.71 4805,9400 4830,9425 5230.04,9425 v1(5310.04,9345)
  Bottom Layer w10: v1(2850,3545) 2851.5,3545 R225.1@3125,3271.5
F_REFCLK1+: R7.1 R16.2 U1.54 | length 476.6
  Layer 1 - Top Layer w12: R7.1@4865,4278.62 4865,4328.62 R16.2@4863.62,4330 4867.56,4330 4873.37,4335.81 4880.27,4342.71 4880.27,4400.27 5040.79,4560.79 U1.54@5040.79,4679
F_REFCLK1-: R4.1 R15.2 U1.55 | length 476.5
  Layer 1 - Top Layer w12: R4.1@4915,4278.62 4916.38,4280 R15.2@4916.38,4330 4912.44,4330 4906.63,4335.81 4900,4342.44 4900,4392.09 5060.52,4552.61 U1.55@5060.52,4679
F_REFCLK1_N: J32.7 R4.2 | length 4055.5
  Layer 1 - Top Layer w12: R4.2@4915,4231.38 4915,4227.44 4900,4212.44 4900,4185 4595,3880 4595,3695 4846,3444 4846,3267.72 4595,3016.72 4595,2143.28 5325.66,1412.62 J32.7@5325.66,819
F_REFCLK1_P: J32.9 R7.2 | length 4055.5
  Layer 1 - Top Layer w12: R7.2@4865,4231.38 4865,4227.44 4880,4212.44 4880,4193.28 4575,3888.28 4575,3686.72 4826,3435.72 4826,3276 4575,3025 4575,2135 5305.66,1404.34 J32.9@5305.66,819
F_REFCLK2+: R62.2 R65.1 U1.24 | length 459.1
  Layer 1 - Top Layer w12: U1.24@5099.89,5171 5099.89,5329.89 5225,5455 5225,5512.56 5238.82,5526.38 5240,5526.38 R62.2@5240,5571.38
F_REFCLK2-: R63.2 R64.1 U1.25 | length 459
  Layer 1 - Top Layer w12: U1.25@5080.16,5171 5080.16,5338.44 5205,5463.28 5205,5512.56 5191.18,5526.38 5190,5526.38 R63.2@5190,5571.38
F_REFCLK2_N: J33.7 R63.1 | length 4061.5
  Layer 1 - Top Layer w12: J33.7@4849.63,9272.88 4849.63,9093.37 5164.88,8778.12 5164.88,6568.17 4860,6263.28 4860,6095 5205,5750 5205,5635.4 5197.97,5628.37 5195.81,5628.37 5190,5622.56 R63.1@5190,5618.62
F_REFCLK2_P: J33.9 R62.1 | length 4061.5
  Layer 1 - Top Layer w12: J33.9@4869.63,9272.88 4869.63,9101.65 5184.88,8786.4 5184.88,6559.88 4880,6255 4880,6103.28 5225,5758.28 5225,5635.4 5232.03,5628.37 5234.19,5628.37 5240,5622.56 R62.1@5240,5618.62
F_SYSREF1+: R20.1 R24.2 U1.49 | length 712.8
  Layer 1 - Top Layer w12: R20.1@4563,4278.62 4563,4327.51 R24.2@4559.35,4331.16 4563.28,4331.16 4569.09,4336.97 4578,4345.88 4578,4495.91 4677.09,4595 4933.09,4595 4942.32,4604.22 U1.49@4942.32,4679
F_SYSREF1-: R19.1 R23.2 U1.50 | length 713.3
  Layer 1 - Top Layer w12: R19.1@4613,4278.62 4613,4327.06 R23.2@4617.1,4331.16 4613.17,4331.16 4597.73,4346.59 4597.73,4487.73 4685.27,4575.27 4941.27,4575.27 4962.05,4596.05 U1.50@4962.05,4679
F_SYSREF1_N: J32.23 R19.2 | length 3818.8
  Layer 1 - Top Layer w12: R19.2@4613,4231.38 4613,4227.44 4598,4212.44 4598,4138 4400,3940 4400,2033.28 5168.18,1265.1 J32.23@5168.18,819
F_SYSREF1_P: J32.25 R20.2 | length 3818.8
  Layer 1 - Top Layer w12: R20.2@4563,4231.38 4563,4227.44 4578,4212.44 4578,4146.28 4380,3948.28 4380,2025 5148.18,1256.82 J32.25@5148.18,819
F_SYSREF2+: R57.1 R61.1 U1.29 | length 438.9
  Layer 1 - Top Layer w12: R57.1@4940,5571.38 4940,5526.38 4938.82,5526.38 4925,5512.56 4925,5448.28 4955,5418.28 4955,5323.28 5001.42,5276.87 U1.29@5001.42,5171
F_SYSREF2-: R55.1 R60.1 U1.30 | length 438.4
  Layer 1 - Top Layer w12: R55.1@4890,5571.38 4890,5527 4905,5512 4905,5440 4935,5410 4935,5315 4981.69,5268.31 U1.30@4981.69,5171
F_SYSREF2_N: J33.23 R55.2 | length 3977.4
  Layer 1 - Top Layer w12: v1(4873.71,8868.09) 4873.71,8865.93 4869.71,8861.93 4869.71,8859.14 4803,8792.44 4803,6473.28 4608,6278.28 4608,6042 4905,5745 4905,5633.62 R55.2@4890,5618.62 ; v1(5006.81,9001.19) 5008.97,9001.19 5012.97,9005.19 5015.76,9005.19 5028.99,9018.43 5028.99,9108.89 5007.85,9130.03 J33.23@5007.85,9272.88
  Bottom Layer w3.75: v1(4873.71,8868.09) 4887.14,8868.09 4944.15,8925.1 5006.81,8987.76 v1(5006.81,9001.19)
F_SYSREF2_P: J33.25 R57.2 | length 3977.4
  Layer 1 - Top Layer w12: 4823,7769.49 4823,8784.15 4883.85,8845 4886.63,8845 4890.63,8849 v1(4892.8,8849) ; 4823,7769.49 4823,6465 4810.03,6452.03 4628,6270 4628,6050.28 4925,5753.28 4925,5633.62 R57.2@4940,5618.62 ; v1(5025.9,8982.1) 5025.9,8984.27 5029.9,8988.27 5029.9,8991.05 5048.99,9010.14 5048.99,9117.17 5027.85,9138.31 J33.25@5027.85,9272.88
  Bottom Layer w3.75: v1(4892.8,8849) 4892.8,8862.43 4952.15,8921.78 5012.46,8982.1 v1(5025.9,8982.1)
FMC_SPI_CLK1: J32.57 U16.14 | length 4339.2
  Layer 1 - Top Layer w10: v1(3075,980) 4790,980 4833.38,936.62 J32.57@4833.38,862.12
  Layer 3 - Signal w10: v1(1570,2325) 1510,2265 1510,2120 1590,2040 2300,2040 2815,1525 2815,1240 v1(3075,980)
  Bottom Layer w8.6: v1(1570,2325) 1580.47,2314.53 U16.14@1620.04,2314.53
FMC_SPI_CLK2: J33.57 U16.13 | length 9643.8
  Layer 1 - Top Layer w8: J33.57@5342.36,9272.88 5342.36,9332.36 v1(5355,9345)
  Layer 3 - Signal w8: v1(1535,2325) 1535,2464 1561,2490 1655,2490 2020.24,2855.24 2020.24,3260.24 2055,3295 2280,3295 2330,3345 2392.81,3345 2420,3372.19 2420,3530 2510,3620 2760,3620 2825,3685 2825,7411.07 4771.97,9358.03 4780,9366.06 4780,9415 4815,9450 5304.05,9450 5355,9399.05 v1(5355,9345)
  Bottom Layer w8: v1(1535,2325) 1565.16,2294.84 U16.13@1620.04,2294.84
FMC_SPI_SCSB1: J32.47 U16.5 | length 4441.4
  Layer 1 - Top Layer w10: v1(3125,1070) 4850,1070 4931.8,988.2 J32.47@4931.8,862.12
  Layer 3 - Signal w10: v1(1805,2275.16) 1749.84,2220 1630,2220 1600,2190 1600,2160 1630,2130 2360,2130 2905,1585 2905,1290 v1(3125,1070)
  Bottom Layer w8: U16.5@1749.96,2275.16 v1(1805,2275.16)
FMC_SPI_SCSB2: J32.60 R188.2 | length 4529.9
  Layer 1 - Top Layer w10: v1(1150,2145) R188.2@1150,2178.5 ; v1(3050,950) 4440,950 4680,710 4800,710 4813.69,696.31 J32.60@4813.69,636.53
  Layer 3 - Signal w10: v1(1150,2145) 1285,2010 2285,2010 2785,1510 2785,1215 v1(3050,950)
FMC_SPI_SCSB3: J33.47 U16.6 | length 9137
  Layer 1 - Top Layer w8: v1(5231.3,9345) 5243.94,9332.36 J33.47@5243.94,9272.88
  Layer 3 - Signal w8: v1(1880,2335) 2290.36,2335 2540.5,2585.15 2540.5,2760.15 2820.5,3040.15 2820.5,3420.5 2900,3500 2900,7380 4825,9305 4845,9325 4950,9325 5000,9375 5201.3,9375 v1(5231.3,9345)
  Bottom Layer w8: U16.6@1749.96,2255.47 1794.99,2255.47 1796.3,2254.16 1813.7,2254.16 1815.01,2255.47 1830.47,2255.47 1860,2285 1860,2315 v1(1880,2335)
FMC_SPI_SCSB4: J33.60 R206.2 | length 9851.5
  Layer 1 - Top Layer w8: J33.60@5362.05,9498.47 5362.05,9438.99 v1(5374.69,9426.35)
  Layer 1 - Top Layer w10: R206.2@1315,2372.09 1377.09,2372.09 1515,2510 2002.1,2510 2022.1,2490 2210,2490 2240,2520 2240,2825 2390,2975 v1(2390,3390)
  Layer 3 - Signal w8: v1(2390,3390) 2390,3560 2480,3650 2755,3650 2800,3695 2800,7421.42 4754.29,9375.71 4754.29,9429.29 4800,9475 5326.04,9475 v1(5374.69,9426.35)
FMC_SPI_SDIO1: J32.49 U16.2 | length 4562.9
  Layer 1 - Top Layer w10: v1(3160,1040) 4840,1040 4912.12,967.88 J32.49@4912.12,862.12
  Layer 3 - Signal w10: v1(1776.42,2353.58) 1638.58,2353.58 1540,2255 1540,2130 1600,2070 2315,2070 2845,1540 2845,1255 3060,1040 v1(3160,1040)
  Bottom Layer w8: U16.2@1749.96,2334.21 1757.05,2334.21 v1(1776.42,2353.58)
FMC_SPI_SDIO2: J33.49 U16.3 | length 9159.5
  Layer 1 - Top Layer w8: J33.49@5263.62,9272.88 5263.62,9332.36 v1(5276.26,9345)
  Layer 3 - Signal w8: v1(1910,2370) 2290,2370 2308.19,2388.19 2515.5,2595.5 2515.5,2770.5 2795.5,3050.5 2795.5,3435.5 2875,3515 2875,7390.36 4807.32,9322.68 4834.65,9350 4935,9350 4985,9400 5221.26,9400 v1(5276.26,9345)
  Bottom Layer w8: U16.3@1749.96,2314.53 1774.53,2314.53 1830,2370 v1(1910,2370)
